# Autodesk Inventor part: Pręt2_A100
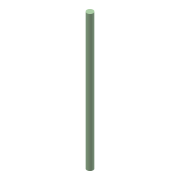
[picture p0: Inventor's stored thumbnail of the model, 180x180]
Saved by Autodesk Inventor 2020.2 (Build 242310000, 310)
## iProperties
Created: 2006-06
Part Number: Pręt2_A100
Document SubType Name: Modeling
Designer: F.Stasiak
Density: 1 g/cm^3
Material: Ogólny
Appearance: Zielony pastelowy
Mass: 2120.58 g
Surface Area: 1735.73 cm^2
Volume: 2120.58 cm^3
Catalog Web Link: www.expertbooks.pl
Manager: www.cadconsulting.pl
Company: Fabian Stasiak CAD Consulting
Author: F.Stasiak
Subject: Zbiór ćwiczeń. Autodesk Inventor 2020. Kurs Professional
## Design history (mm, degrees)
sketch "Szkic1"
  geometry: C1 r 25 at (0, 0); 1 further point
  constraints: 1 centre point, 1 coincident
  dimensions: "d0" = 50 diameter of C1
extrude "Wyciągnięcie proste1" new body sketch "Szkic1" distance "d1" = 1080; taper "d2" = 0 deg
node "Bryła1"
node "Korpusy bryłowe"
node "Korpusy powierzchniowe"
